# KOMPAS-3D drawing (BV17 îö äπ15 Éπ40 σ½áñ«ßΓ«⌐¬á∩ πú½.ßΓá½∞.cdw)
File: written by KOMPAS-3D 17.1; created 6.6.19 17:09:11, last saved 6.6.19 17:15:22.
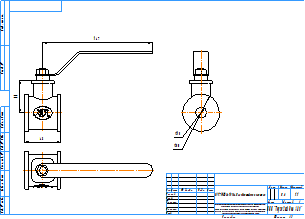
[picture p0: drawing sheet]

Sheet 1: A3, landscape

Title block, sheet 1: name: BV17 МФ Ду15 Ру40 хладостойкая угл.сталь; material: Сталь 20  ГОСТ 1050-2013; mass: 0,6; sheets: 1; sheet format: A3; stored path: \\adlc.lan\data\АДЛ_ПКД\3D-модели\ADL production\Краны шаровые серии BV\BV17 МФ хладостойкая угл.сталь Ру40\KOMPAS 2D\BV17 МФ Ду15 Ру40 хладостойкая угл.сталь.cdw

Views: Вид 1, Проекционный вид 2, Проекционный вид 3
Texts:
  kka
  adl
  Рама для чертежей
  Лит-Масса-Масштаб
  Материал-Предприятие
  Масштаб
  Изм.
  Лист
  № докум.
  Подп.
  Дата
  Лит.
  Разраб.
  Пров.
  Т.контр.
  Листов
  Внимание! Данный продукт является объектом авторского права ООО «Торговый Дом АДЛ».
  Запрещается изменение, копирование, распространение
  (в том числе путем копирования на другие сайты и ресурсы в Интернете)
  или любое иное использование информации и объектов без предварительного
  согласия правообладателя (ООО «Торговый Дом АДЛ»).
  Н.контр.
  Утв.
  ООО "Торговый дом АДЛ"
  Изменение
  Номер документа
  Подпись
  Обозначение документа
  Наименование изделия
  Масса изделия по ГОСТ 2.109-73
  Порядковый номер листа
  Общее количество листов в документе
  Характер работы, выполненной лицом, подписавшим документ
  Наименование или индекс предприятия, выпускающего документ
  Инв. № подл.
  Подп. и дата
  Взам. инв. №
  Инв. № дубл.
  Инвентарный номер подлинника по ГОСТ 2.501-68
  Подпись принявшего подлинник в отдел технической документации
  Инвентарный номер подлинника, взамен которого выпущен данный подлинник
  Инвентарный номер дубликата по ГОСТ 2.502-68
  Подпись принявшего дубликат в отдел технической документации
  Справ. №
  Перв. примен.
  Обозначение документа, взамен или на основании которого выпущен данный документ
  Обозначение документа, в котором впервые записан данный документ
  Подпись лица, копировавшего чертеж
  Обозначение формата листа
  !Рама для чертежа
Dimensions and other numbers on the sheet: 48; 44; 147; 15; 50; 1:1; 1; 0,6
